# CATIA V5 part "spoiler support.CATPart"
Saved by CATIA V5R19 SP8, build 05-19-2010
Part number: spoiler support
Bounding box of the stored display mesh (mm): x 17.067 to 150.522, y 36.2 to 76, z 123.035 to 218.167
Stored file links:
  G:\EU_thinkMotion\CFAO_2010\MMS_groupe1\MMS_groupe1\A reprendre\gduval\CFAO kinematic ok\spoiler support.CATPart
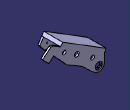
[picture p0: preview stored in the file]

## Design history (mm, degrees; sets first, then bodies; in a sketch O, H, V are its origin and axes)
Body1 (main body)
  Plane1: stored without definition
  Point1: stored without definition
  Point2: stored without definition
  Line1: stored without definition
  Sketch1 on Plane1, origin (0, 72.4, 0), H (-1, 0, 0), V (0, 0, 1)
    line L1 (-108.345, 214.474) -> (-17.067, 157.999)
    point P1 (-108.345, 214.474)
    point P2 (-17.067, 157.999)
    reference projected point E1 (-17.067, 157.999) from Point1
    reference projected point E2 (-108.345, 214.474) from Point2
    line L2 (-17.067, 157.999) -> (-21.1523, 151.3961)
    point P3 (-21.1523, 151.3961)
    line L3 (-108.345, 214.474) -> (-112.8658, 208.5138)
    line L4 (-112.8658, 208.5138) -> (-129.4784, 218.1674)
    line L5 (-133.7128, 218.1674) -> (-150.5223, 204.013)
    point P7 (-150.5223, 204.013)
    line L6 (-133.7128, 218.1674) -> (-129.4784, 218.1674)
    line L7 (-150.5223, 204.013) -> (-138.0058, 190.4556)
    point P8 (-150.5223, 204.013)
    point P9 (-138.0058, 190.4556)
    line L8 (-138.0058, 190.4556) -> (-127.4885, 199.3116)
    point P10 (-138.0058, 190.4556)
    line L9 (-127.4885, 199.3116) -> (-104.1242, 174.0041)
    point P12 (-104.1242, 174.0041)
    spline S1 through (-104.1242, 174.0041) (-100.1039, 169.6495) (-88.0156, 162.4747) (-79.7211, 157.4979) (-69.4359, 151.3961) (-62.0256, 145.4429) (-52.8463, 135.9316) (-48.3117, 132.0607) (-28.4048, 123.5448) (-22.5433, 128.0792) (-21.1523, 138.1435) (-21.1523, 143.231) (-21.1523, 151.3961)
    point P13 (-104.1242, 174.0041)
    point P14 (-100.1039, 169.6495)
    point P15 (-21.1523, 151.3961)
    coincidence: P2 E1, P1 E2, P8 L5, P10 L7, P13 P12, P14 L9, P15 P3, P7 P8, P9 P10
    perpendicularity: L2 L1
    horizontal: L6 H
    parallelism: L8 L5, L9 L7
  Pad1: profile Sketch1, direction (0, 1, 0), length 3.6
  Line2: stored without definition
  Sketch2 on end face of Pad1, origin (78.802, 76, 178.053), H (1, 0, 0), V (0, 0, -1)
    point P1 (0, 0)
    intersected point E1 (0, 0) from Line1
    coincidence: E1 P1
  Hole1: placed by Sketch2, at (78.802, 76, 178.053) direction (0, -1, 0), diameter 10, through (limit type 6)
  Line3: stored without definition
  Sketch3 on start face of Pad1, origin (45.815, 72.4, 155.401), H (1, 0, 0), V (0, 0, 1)
    point P1 (0, 0)
  Hole2: placed by Sketch3, at (45.815, 72.4, 155.401) direction (0, 1, 0), diameter 8, through (limit type 6)
  Sketch4 on start face of Pad1, origin (105.437, 72.4, 194.272), H (1, 0, 0), V (0, 0, 1)
    point P1 (0, 0)
  Hole3: placed by Sketch4, at (105.437, 72.4, 194.272) direction (0, 1, 0), diameter 8, through (limit type 6)
  Plane2: stored without definition
  Sketch5 on start face of Pad1, origin (0, 72.4, 0), H (1, 0, 0), V (0, 0, 1)
    line L1 (108.345, 214.474) -> (112.8658, 208.5138)
    point P1 (108.345, 214.474)
    point P2 (112.8658, 208.5138)
    reference projected line E1 (108.345, 214.474) -> (112.8658, 208.5138) from edge [start face of Pad1 | face of Pad1 from Sketch1.L3]
    reference projected point E2 (108.345, 214.474) from vertex [face of Pad1 from Sketch1.L1 | start face of Pad1 | face of Pad1 from Sketch1.L3]
    reference projected point E3 (112.8658, 208.5138) from vertex [face of Pad1 from Sketch1.L4 | start face of Pad1 | face of Pad1 from Sketch1.L3]
    line L2 (108.345, 214.474) -> (17.067, 157.999)
    point P3 (17.067, 157.999)
    reference projected point E4 (17.067, 157.999) from vertex [face of Pad1 from Sketch1.L1 | start face of Pad1 | face of Pad1 from Sketch1.L2]
    line L3 (17.067, 157.999) -> (21.1523, 151.3961)
    point P4 (21.1523, 151.3961)
    reference projected point E5 (21.1523, 151.3961) from vertex [face of Pad1 from Sketch1.L2 | start face of Pad1 | face of Pad1 from Sketch1.S1]
    line L4 (21.1523, 151.3961) -> (112.8658, 208.5138)
    coincidence: L1 E1, P1 E2, P2 E3, P3 E4, P4 E5
    perpendicularity: L3 L2
  Pad2: profile Sketch5, direction (0, -1, 0), up to Plane2
  Sketch6 on end face of Pad2, origin (0, 36.2, 0), H (1, 0, 0), V (0, 0, 1)
    line L1 (21.1523, 151.3961) -> (112.8658, 208.5138)
    point P1 (21.1523, 151.3961)
    point P2 (112.8658, 208.5138)
    reference projected point E1 (112.8658, 208.5138) from vertex [face of Pad2 from Sketch5.L1 | face of Pad2 from Sketch5.L4 | end face of Pad2]
    reference projected point E2 (21.1523, 151.3961) from vertex [face of Pad2 from Sketch5.L4 | face of Pad2 from Sketch5.L3 | end face of Pad2]
    spline S1 through (21.1523, 151.3961) (44.8409, 135.8442) (62.8783, 148.2317) (79.1771, 159.0979) (101.3436, 174.9625) (120.6848, 195.9588)
    line L2 (112.8658, 208.5138) -> (120.6848, 195.9588)
    point P3 (120.6848, 195.9588)
    point P4 (21.1523, 151.3961)
    point P5 (120.6848, 195.9588)
    coincidence: P2 E1, P1 E2, P4 P1, P3 P5
    perpendicularity: L2 L1
  Pad3: profile Sketch6, direction (0, 1, 0), length 4
  Sketch7 on face of Pad3, origin (105.437, 36.2, 194.272), H (1, 0, 0), V (0, 0, 1)
    point P1 (0, 0)
    intersected point E1 (0, 0) from Line3
    coincidence: E1 P1
  Hole4: placed by Sketch7, at (105.437, 36.2, 194.272) direction (0, 1, 0), diameter 3, through (limit type 6)
  Sketch8 on face of Pad3, origin (45.815, 36.2, 155.401), H (1, 0, 0), V (0, 0, 1)
    point P1 (0, 0)
    intersected point E1 (0, 0) from Line2
    coincidence: E1 P1
  Hole5: placed by Sketch8, at (45.815, 36.2, 155.401) direction (0, 1, 0), diameter 3, through (limit type 6)
  Line4: stored without definition
  Sketch9 on face of Pad3, origin (0, 36.2, 0), H (1, 0, 0), V (0, 0, 1)
    line L1 (117.8351, 177.4334) -> (99.0616, 159.6834)
    point P1 (117.8351, 177.4334)
    point P2 (99.0616, 159.6834)
    spline S1 through (117.8351, 177.4334) (111.6911, 181.8709) (97.1843, 183.5776) (90.0162, 173.5079) (93.2589, 163.2675) (99.0616, 159.6834)
    point P3 (117.8351, 177.4334)
    point P4 (99.0616, 159.6834)
    coincidence: P3 P1, P4 P2
  Pocket1: profile Sketch9, direction (0, 1, 0), up to end face of Pad3
  Sketch10 on end face of Pad1, origin (32.689, 76, 134.301), H (1, 0, 0), V (0, 0, -1)
    point P1 (0, 0)
    intersected point E1 (0, 0) from Line4
    coincidence: E1 P1
  Hole6: placed by Sketch10, at (32.689, 76, 134.301) direction (0, -1, 0), diameter 10, through (limit type 6), counterbore diameter 15, counterbore depth 2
